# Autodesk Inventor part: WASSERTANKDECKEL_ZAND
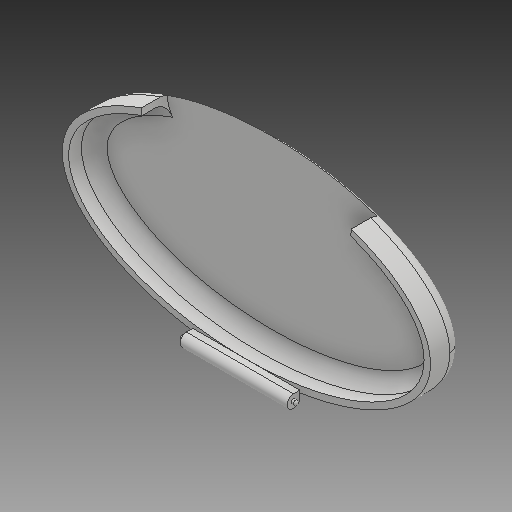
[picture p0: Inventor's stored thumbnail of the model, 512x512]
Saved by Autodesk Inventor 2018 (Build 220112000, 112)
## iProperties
Created: 2019-01
Part Number: WASSERTANKDECKEL_ZAND
Material: Polypropylene (PP)
Document SubType Name: Modeling
Designer: zand
Density: 0.902188 g/cm^3
Appearance: Vorgabe
Mass: 42.5759 g
Surface Area: 314.428 cm^2
Volume: 47.1919 cm^3
Author: zand
Revision Number: 32LAST_VERSION
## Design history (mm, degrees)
feature "Basis1"
node "Volumenkörper1"
